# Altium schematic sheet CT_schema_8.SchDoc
size 277 x 170 mm
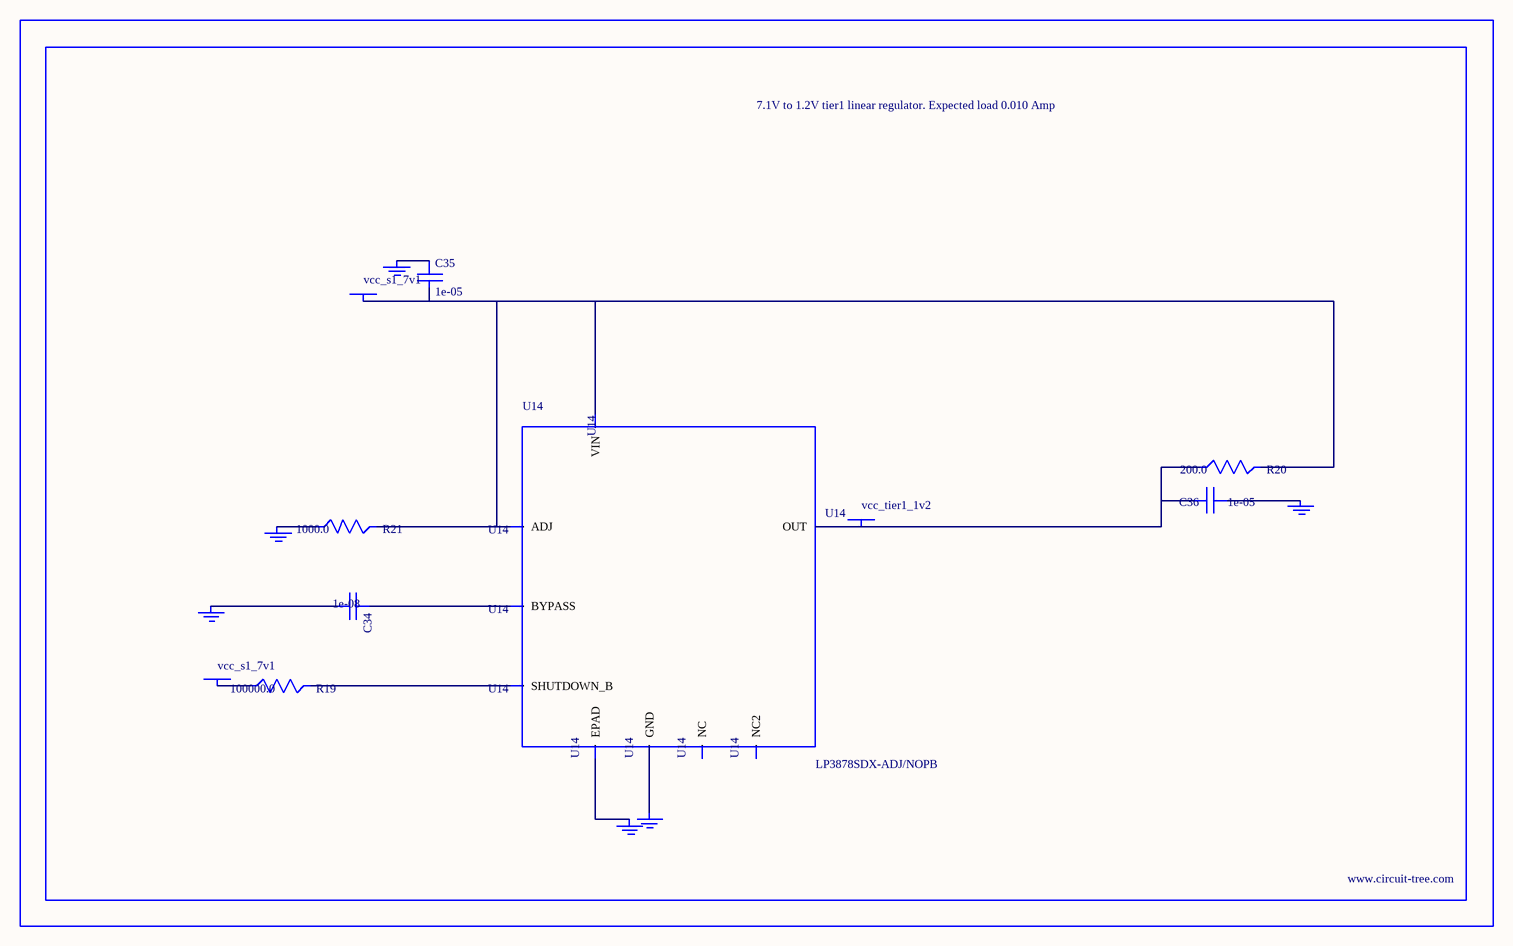
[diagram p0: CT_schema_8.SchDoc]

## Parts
BORDER7  (no value)
C34  1e-08  [C0402]
C35  1e-05  [C1206]
C36  1e-05  [C0805]
GND_INSTANCE_7_0  (no value)
GND_INSTANCE_7_1  (no value)
GND_INSTANCE_7_2  (no value)
GND_INSTANCE_7_3  (no value)
GND_INSTANCE_7_4  (no value)
GND_INSTANCE_7_5  (no value)
POWER_INSTANCE_7_0  vcc_s1_7v1
POWER_INSTANCE_7_1  vcc_s1_7v1
POWER_INSTANCE_7_2  vcc_tier1_1v2
R19  100000.0  [R0603]
R20  200.0  [R0603]
R21  1000.0  [R0603]
U14  LP3878SDX-ADJ/NOPB  [WSON-8]

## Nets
NetC34_1: C34.1 U14.1(BYPASS)
NetC34_2: C34.2 GND_INSTANCE_7_0.0(GND)
NetC35_1: C35.1 GND_INSTANCE_7_1.0(GND)
NetC35_2: C35.2 POWER_INSTANCE_7_0.0(PWR) R20.2 R21.2 U14.4(VIN) U14.6(ADJ)
NetC36_1: C36.1 GND_INSTANCE_7_2.0(GND)
NetC36_2: C36.2 POWER_INSTANCE_7_2.0(PWR) R20.1 U14.5(OUT)
NetGND_INSTANCE_7_3_0: GND_INSTANCE_7_3.0(GND) R21.1
NetGND_INSTANCE_7_4_0: GND_INSTANCE_7_4.0(GND) U14.PAD(EPAD)
NetGND_INSTANCE_7_5_0: GND_INSTANCE_7_5.0(GND) U14.3(GND)
NetPOWER_INSTANCE_7_1_0: POWER_INSTANCE_7_1.0(PWR) R19.1
NetR19_2: R19.2 U14.8(SHUTDOWN_B)

Not connected (* = marked no-connect by the designer): U14 2(NC) 7(NC2)

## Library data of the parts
BORDER7 = BORDER_PAGE7
C34 = C0402C103K3RAC
C35 = C1206C106K3RACTU
C36 = GRM219R60J106ME19D
GND_INSTANCE_7_0-GND_INSTANCE_7_5 = GND
POWER_INSTANCE_7_0-POWER_INSTANCE_7_2 = PWR
R19 = RC0603JR-07100KL
R20 = RC0603JR-07200RL
R21 = RC0603JR-071KL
